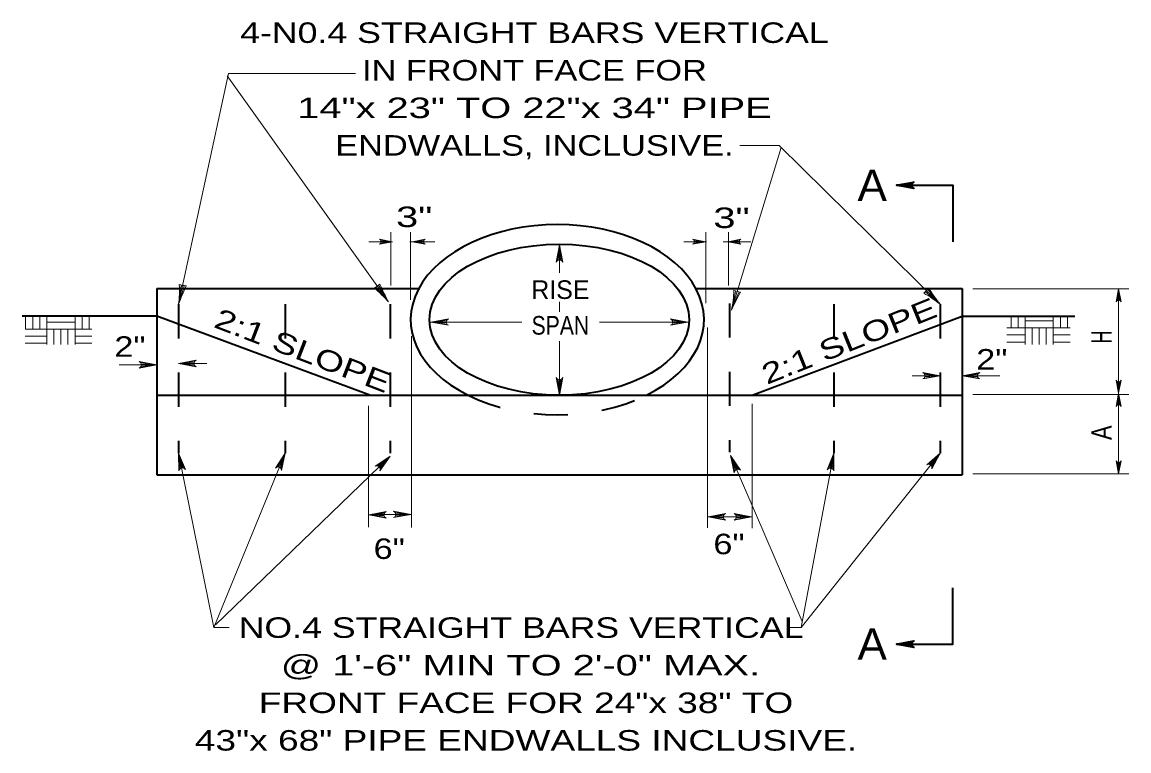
# Model space of a CAD drawing. Extents: x 394.95 to 401.96, y -76.51 to -66.78.
# Drawn here: x 395.195 to 398.432, y -71.634 to -69.501 of the extents above; entities that cross this region are included whole.
import ezdxf
from ezdxf.enums import TextEntityAlignment as Align

# ---------------------------------------------------------------- set-up
doc = ezdxf.new("R2010")
doc.units = 0
doc.header["$LTSCALE"] = 0.024
doc.linetypes.add('LONG_DASHED', pattern=[7.5, 6, -1.5])
doc.linetypes.add('MEDIUM_DASHED', pattern=[4.5, 3, -1.5])
for name, color, linetype, lineweight in [('1', 7, 'LONG_DASHED', 35), ('10', 7, 'Continuous', 13), ('13', 7, 'Continuous', 25), ('6', 7, 'Continuous', 13)]:
    doc.layers.add(name, color=color, linetype=linetype, lineweight=lineweight)
doc.layers.add('12', color=7, linetype='Continuous')

msp = doc.modelspace()

# ---------------------------------------------------------------- linework, layer by layer
at = {"layer": '1', "linetype": 'Continuous'}
for p, q in [((395.58852, -70.28099), (395.58852, -70.82641)), ((395.58852, -70.28099), (396.35718, -70.28099)), ((397.16762, -70.28099), (397.94435, -70.28099)), ((397.94435, -70.28099), (397.94435, -70.82641)), ((395.58852, -70.59266), (397.94435, -70.59266)), ((395.58852, -70.82641), (397.94435, -70.82641))]:
    msp.add_line(p, q, dxfattribs=at)
at = {"layer": '1', "linetype": 'MEDIUM_DASHED'}
for p, q in [((395.65269, -70.32682), (395.65269, -70.76224)), ((395.96435, -70.32682), (395.96435, -70.76224)), ((396.27116, -70.32682), (396.27116, -70.76224)), ((397.26408, -70.32446), (397.26408, -70.75987)), ((397.56852, -70.32682), (397.56852, -70.76224)), ((397.88019, -70.32682), (397.88019, -70.76224))]:
    msp.add_line(p, q, dxfattribs=at)
at = {"layer": '1', "linetype": 'Continuous'}
for points in [[(396.21231, -70.59266), (395.58852, -70.36187), (395.19491, -70.36187)], [(397.33013, -70.59266), (397.94435, -70.36187), (398.27364, -70.36187)]]:
    msp.add_lwpolyline(points, dxfattribs=at)
msp.add_ellipse((396.76029, -70.37184), major_axis=(0.42908, 0), ratio=0.648289, start_param=5.3652919, end_param=10.3420118, dxfattribs=at)
msp.add_ellipse((396.76595, -70.37184), major_axis=(0.37952, 0), ratio=0.582646, dxfattribs=at)
at = {"layer": '1', "linetype": 'MEDIUM_DASHED'}
msp.add_ellipse((396.76029, -70.37184), major_axis=(0.42908, 0), ratio=0.648289, start_param=4.0592877, end_param=5.364093, dxfattribs=at)
at = {"layer": '10'}
for p, q in [((396.26643, -70.31973), (395.79427, -69.65786)), ((397.26978, -70.34359), (397.41525, -69.86823)), ((397.40866, -69.86173), (397.29401, -69.86173)), ((397.88019, -70.32682), (397.40866, -69.86173)), ((396.27561, -70.14353), (396.20899, -70.14353)), ((396.27352, -70.27182), (396.27352, -70.11599)), ((396.3292, -70.14349), (396.3906, -70.14349)), ((396.33118, -70.31369), (396.33118, -70.11599)), ((396.33546, -70.14349), (396.40246, -70.14349)), ((397.1966, -70.14353), (397.12998, -70.14353)), ((397.19509, -70.32348), (397.19509, -70.11599)), ((397.24547, -70.14349), (397.30687, -70.14349)), ((397.2588, -70.14349), (397.3258, -70.14349)), ((397.2612, -70.27182), (397.2612, -70.11599)), ((395.65567, -70.30754), (395.65979, -70.27209)), ((395.65834, -70.3087), (395.66931, -70.27414)), ((396.25684, -70.30333), (396.23868, -70.27196)), ((396.25418, -70.30454), (396.23074, -70.27761)), ((397.2744, -70.32464), (397.2815, -70.28966)), ((397.27697, -70.32602), (397.29081, -70.29251)), ((397.86551, -70.31396), (397.8378, -70.29147)), ((397.86793, -70.31232), (397.84465, -70.28453)), ((398.43192, -70.28135), (397.97555, -70.28135)), ((398.40191, -70.28135), (398.40191, -70.4774)), ((396.76644, -70.34891), (396.76644, -70.31994)), ((396.3906, -70.37871), (396.65682, -70.37871)), ((396.88349, -70.37871), (397.14227, -70.37871)), ((397.1993, -70.39502), (397.1993, -70.98091)), ((396.33357, -70.42042), (396.33357, -70.97971)), ((396.76644, -70.59266), (396.76644, -70.43484)), ((395.73519, -70.50032), (395.65269, -70.50032)), ((398.40191, -70.4774), (398.40191, -70.5874)), ((395.58852, -70.50414), (395.47852, -70.50414)), ((396.76644, -70.59266), (396.75956, -70.54533)), ((396.76644, -70.54507), (396.76644, -70.56524)), ((397.88019, -70.5358), (397.79769, -70.5358)), ((398.05435, -70.5358), (397.94435, -70.5358)), ((398.43192, -70.59068), (397.97555, -70.59068)), ((398.40191, -70.5874), (398.40191, -70.71321)), ((396.20785, -70.62364), (396.20785, -70.97921)), ((397.33009, -70.61855), (397.33009, -70.98232)), ((398.40191, -70.71321), (398.40191, -70.82321)), ((395.75603, -71.27315), (395.65269, -70.76224)), ((395.96435, -70.76224), (395.75603, -71.27315)), ((396.21146, -70.82933), (396.27116, -70.7717)), ((397.33946, -70.93832), (397.26645, -70.76933)), ((397.56852, -70.76224), (397.47299, -71.27315)), ((397.473, -71.27314), (397.88019, -70.76224)), ((398.43192, -70.82321), (397.97555, -70.82321)), ((395.76014, -71.26507), (396.21146, -70.82933)), ((396.25295, -70.94298), (396.20848, -70.94298)), ((396.33258, -70.94171), (396.22258, -70.94171)), ((397.30832, -70.94866), (397.20123, -70.94866)), ((397.32832, -70.94856), (397.2822, -70.94856)), ((397.47635, -71.25516), (397.33946, -70.93832)), ((395.79999, -71.27315), (395.75603, -71.27315)), ((397.47299, -71.27315), (397.43852, -71.27315))]:
    msp.add_line(p, q, dxfattribs=at)
for points in [[(396.17019, -69.65082), (395.79836, -69.65082), (395.65269, -70.32682)], [(396.27829, -70.14349), (396.23983, -70.1507), (396.2428, -70.14865), (396.24432, -70.14607), (396.24477, -70.14349), (396.24432, -70.14092), (396.2428, -70.13833), (396.23983, -70.13628), (396.27829, -70.14349), (396.2428, -70.13833), (396.24432, -70.14092), (396.27829, -70.14349), (396.24477, -70.14349), (396.24432, -70.14607), (396.27829, -70.14349), (396.2428, -70.14865)], [(396.33546, -70.14349), (396.3739, -70.13628), (396.37095, -70.13833), (396.36941, -70.14092), (396.36897, -70.14349), (396.36941, -70.14607), (396.37095, -70.14865), (396.3739, -70.1507), (396.33546, -70.14349), (396.37095, -70.14865), (396.36941, -70.14607), (396.33546, -70.14349), (396.36897, -70.14349), (396.36941, -70.14092), (396.33546, -70.14349), (396.37095, -70.13833)], [(397.19455, -70.14349), (397.15609, -70.1507), (397.15906, -70.14865), (397.16058, -70.14607), (397.16103, -70.14349), (397.16058, -70.14092), (397.15906, -70.13833), (397.15609, -70.13628), (397.19455, -70.14349), (397.15906, -70.13833), (397.16058, -70.14092), (397.19455, -70.14349), (397.16103, -70.14349), (397.16058, -70.14607), (397.19455, -70.14349), (397.15906, -70.14865)], [(397.2588, -70.14349), (397.29724, -70.13628), (397.29429, -70.13833), (397.29275, -70.14092), (397.29231, -70.14349), (397.29275, -70.14607), (397.29429, -70.14865), (397.29724, -70.1507), (397.2588, -70.14349), (397.29429, -70.14865), (397.29275, -70.14607), (397.2588, -70.14349), (397.29231, -70.14349), (397.29275, -70.14092), (397.2588, -70.14349), (397.29429, -70.13833)], [(396.76644, -70.23516), (396.76644, -70.15266), (396.77604, -70.20393), (396.77331, -70.19997), (396.76988, -70.19793), (396.76644, -70.19734), (396.763, -70.19793), (396.75956, -70.19997), (396.75682, -70.20393), (396.76644, -70.15266), (396.75956, -70.19997), (396.763, -70.19793), (396.76644, -70.15266), (396.76644, -70.19734), (396.76988, -70.19793), (396.76644, -70.15266), (396.77331, -70.19997)], [(398.40191, -70.28135), (398.40911, -70.3198), (398.40706, -70.31684), (398.40449, -70.31531), (398.40191, -70.31488), (398.39933, -70.31531), (398.39675, -70.31684), (398.39469, -70.3198), (398.40191, -70.28135), (398.39675, -70.31684), (398.39933, -70.31531), (398.40191, -70.28135), (398.40191, -70.31488), (398.40449, -70.31531), (398.40191, -70.28135), (398.40706, -70.31684)], [(396.3906, -70.37871), (396.44186, -70.36909), (396.43792, -70.37183), (396.43588, -70.37527), (396.43529, -70.37871), (396.43588, -70.38215), (396.43792, -70.38558), (396.44186, -70.38832), (396.3906, -70.37871), (396.43792, -70.38558), (396.43588, -70.38215), (396.3906, -70.37871), (396.43529, -70.37871), (396.43588, -70.37527), (396.3906, -70.37871), (396.43792, -70.37183)], [(397.14227, -70.37871), (397.091, -70.38832), (397.09495, -70.38558), (397.09699, -70.38215), (397.09758, -70.37871), (397.09699, -70.37527), (397.09495, -70.37183), (397.091, -70.36909), (397.14227, -70.37871), (397.09495, -70.37183), (397.09699, -70.37527), (397.14227, -70.37871), (397.09758, -70.37871), (397.09699, -70.38215), (397.14227, -70.37871), (397.09495, -70.38558)], [(395.58852, -70.50414), (395.53725, -70.51375), (395.5412, -70.51101), (395.54324, -70.50757), (395.54383, -70.50414), (395.54324, -70.5007), (395.5412, -70.49726), (395.53725, -70.49452), (395.58852, -70.50414), (395.5412, -70.49726), (395.54324, -70.5007), (395.58852, -70.50414), (395.54383, -70.50414), (395.54324, -70.50757), (395.58852, -70.50414), (395.5412, -70.51101)], [(395.65269, -70.50032), (395.70395, -70.49071), (395.7, -70.49345), (395.69796, -70.49689), (395.69737, -70.50032), (395.69796, -70.50376), (395.7, -70.5072), (395.70395, -70.50994), (395.65269, -70.50032), (395.7, -70.5072), (395.69796, -70.50376), (395.65269, -70.50032), (395.69737, -70.50032), (395.69796, -70.49689), (395.65269, -70.50032), (395.7, -70.49345)], [(397.88019, -70.53579), (397.82892, -70.54541), (397.83286, -70.54267), (397.83491, -70.53923), (397.8355, -70.53579), (397.83491, -70.53235), (397.83286, -70.52892), (397.82892, -70.52618), (397.88019, -70.53579), (397.83286, -70.52892), (397.83491, -70.53235), (397.88019, -70.53579), (397.8355, -70.53579), (397.83491, -70.53923), (397.88019, -70.53579), (397.83286, -70.54267)], [(397.94435, -70.53579), (397.99561, -70.52618), (397.99167, -70.52892), (397.98962, -70.53235), (397.98904, -70.53579), (397.98962, -70.53923), (397.99167, -70.54267), (397.99561, -70.54541), (397.94435, -70.53579), (397.99167, -70.54267), (397.98962, -70.53923), (397.94435, -70.53579), (397.98904, -70.53579), (397.98962, -70.53235), (397.94435, -70.53579), (397.99167, -70.52892)], [(398.40191, -70.5874), (398.39469, -70.54896), (398.39675, -70.55192), (398.39933, -70.55345), (398.40191, -70.55389), (398.40449, -70.55345), (398.40706, -70.55192), (398.40911, -70.54896), (398.40191, -70.5874), (398.40706, -70.55192), (398.40449, -70.55345), (398.40191, -70.5874), (398.40191, -70.55389), (398.39933, -70.55345), (398.40191, -70.5874), (398.39675, -70.55192)], [(398.40191, -70.5874), (398.40911, -70.62585), (398.40706, -70.62289), (398.40449, -70.62136), (398.40191, -70.62092), (398.39933, -70.62136), (398.39675, -70.62289), (398.39469, -70.62585), (398.40191, -70.5874), (398.39675, -70.62289), (398.39933, -70.62136), (398.40191, -70.5874), (398.40191, -70.62092), (398.40449, -70.62136), (398.40191, -70.5874), (398.40706, -70.62289)], [(395.65269, -70.76224), (395.67227, -70.81057), (395.66879, -70.80725), (395.66503, -70.80594), (395.66154, -70.80603), (395.65829, -70.80729), (395.65532, -70.80998), (395.65342, -70.81439), (395.65269, -70.76224), (395.65532, -70.80998), (395.65829, -70.80729), (395.65269, -70.76224), (395.66154, -70.80603), (395.66503, -70.80594), (395.65269, -70.76224), (395.66879, -70.80725)], [(395.96435, -70.76224), (395.9539, -70.81333), (395.95284, -70.80865), (395.95044, -70.80546), (395.94748, -70.80361), (395.94407, -70.80286), (395.94011, -70.80346), (395.93609, -70.80608), (395.96435, -70.76224), (395.94011, -70.80346), (395.94407, -70.80286), (395.96435, -70.76224), (395.94748, -70.80361), (395.95044, -70.80546), (395.96435, -70.76224), (395.95284, -70.80865)], [(396.27116, -70.7717), (396.24095, -70.81422), (396.24189, -70.8095), (396.24096, -70.80561), (396.239, -70.80274), (396.2362, -70.80067), (396.23233, -70.79961), (396.22759, -70.8004), (396.27116, -70.7717), (396.23233, -70.79961), (396.2362, -70.80067), (396.27116, -70.7717), (396.239, -70.80274), (396.24096, -70.80561), (396.27116, -70.7717), (396.24189, -70.8095)], [(397.26645, -70.76933), (397.29559, -70.81258), (397.29152, -70.81003), (397.28755, -70.80953), (397.28416, -70.81035), (397.28125, -70.81226), (397.27891, -70.81549), (397.27795, -70.8202), (397.26645, -70.76933), (397.27891, -70.81549), (397.28125, -70.81226), (397.26645, -70.76933), (397.28416, -70.81035), (397.28755, -70.80953), (397.26645, -70.76933), (397.29152, -70.81003)], [(397.56852, -70.76224), (397.56854, -70.8144), (397.56658, -70.81001), (397.56357, -70.80737), (397.5603, -70.80617), (397.55682, -70.80611), (397.55306, -70.80748), (397.54965, -70.81086), (397.56852, -70.76224), (397.55306, -70.80748), (397.55682, -70.80611), (397.56852, -70.76224), (397.5603, -70.80617), (397.56357, -70.80737), (397.56852, -70.76224), (397.56658, -70.81001)], [(397.88019, -70.76224), (397.84071, -70.79634), (397.84532, -70.79496), (397.84927, -70.79551), (397.85233, -70.79719), (397.85465, -70.79979), (397.85606, -70.80353), (397.85575, -70.80831), (397.88019, -70.76224), (397.85606, -70.80353), (397.85465, -70.79979), (397.88019, -70.76224), (397.85233, -70.79719), (397.84927, -70.79551), (397.88019, -70.76224), (397.84532, -70.79496)], [(398.40191, -70.82321), (398.39469, -70.78477), (398.39675, -70.78773), (398.39933, -70.78926), (398.40191, -70.7897), (398.40449, -70.78926), (398.40706, -70.78773), (398.40911, -70.78477), (398.40191, -70.82321), (398.40706, -70.78773), (398.40449, -70.78926), (398.40191, -70.82321), (398.40191, -70.7897), (398.39933, -70.78926), (398.40191, -70.82321), (398.39675, -70.78773)], [(396.20848, -70.94298), (396.25974, -70.93336), (396.25579, -70.9361), (396.25375, -70.93954), (396.25317, -70.94298), (396.25375, -70.94642), (396.25579, -70.94985), (396.25974, -70.95259), (396.20848, -70.94298), (396.25579, -70.94985), (396.25375, -70.94642), (396.20848, -70.94298), (396.25317, -70.94298), (396.25375, -70.93954), (396.20848, -70.94298), (396.25579, -70.9361)], [(396.33258, -70.94171), (396.28131, -70.95132), (396.28526, -70.94858), (396.2873, -70.94515), (396.2879, -70.94171), (396.2873, -70.93827), (396.28526, -70.93483), (396.28131, -70.93209), (396.33258, -70.94171), (396.28526, -70.93483), (396.2873, -70.93827), (396.33258, -70.94171), (396.2879, -70.94171), (396.2873, -70.94515), (396.33258, -70.94171), (396.28526, -70.94858)], [(397.20123, -70.94866), (397.25249, -70.93904), (397.24854, -70.94178), (397.2465, -70.94522), (397.24592, -70.94866), (397.2465, -70.95209), (397.24854, -70.95553), (397.25249, -70.95827), (397.20123, -70.94866), (397.24854, -70.95553), (397.2465, -70.95209), (397.20123, -70.94866), (397.24592, -70.94866), (397.2465, -70.94522), (397.20123, -70.94866), (397.24854, -70.94178)], [(397.32832, -70.94856), (397.27705, -70.95818), (397.281, -70.95544), (397.28304, -70.952), (397.28364, -70.94856), (397.28304, -70.94513), (397.281, -70.94169), (397.27705, -70.93895), (397.32832, -70.94856), (397.281, -70.94169), (397.28304, -70.94513), (397.32832, -70.94856), (397.28364, -70.94856), (397.28304, -70.952), (397.32832, -70.94856), (397.281, -70.95544)]]:
    msp.add_lwpolyline(points, dxfattribs=at)
at = {"layer": '10', "lineweight": 35}
for points in [[(397.75185, -69.97849), (397.80311, -69.96887), (397.79917, -69.97161), (397.79712, -69.97505), (397.79654, -69.97849), (397.79712, -69.98193), (397.79917, -69.98536), (397.80311, -69.9881), (397.75185, -69.97849), (397.79917, -69.98536), (397.79712, -69.98193), (397.75185, -69.97849), (397.79654, -69.97849), (397.79712, -69.97505), (397.75185, -69.97849), (397.79917, -69.97161)], [(397.75185, -69.97849), (397.91685, -69.97849), (397.91685, -70.14349)], [(397.75185, -71.32141), (397.91685, -71.32141), (397.91685, -71.15641)], [(397.75185, -71.32141), (397.80311, -71.31179), (397.79917, -71.31453), (397.79712, -71.31797), (397.79654, -71.32141), (397.79712, -71.32484), (397.79917, -71.32828), (397.80311, -71.33102), (397.75185, -71.32141), (397.79917, -71.32828), (397.79712, -71.32484), (397.75185, -71.32141), (397.79654, -71.32141), (397.79712, -71.31797), (397.75185, -71.32141), (397.79917, -71.31453)]]:
    msp.add_lwpolyline(points, dxfattribs=at)
at = {"layer": '10'}
for points in [[(396.76644, -70.59266), (396.75682, -70.5414), (396.75956, -70.54533), (396.763, -70.54738), (396.76644, -70.54797), (396.76988, -70.54738), (396.77331, -70.54533), (396.77604, -70.5414)], [(396.76644, -70.59266), (396.76644, -70.54797), (396.763, -70.54738)], [(396.76644, -70.59266), (396.77331, -70.54533), (396.76988, -70.54738)]]:
    msp.add_lwpolyline(points, close=True, dxfattribs=at)
for centre, radius, start, end in [((395.2625, -70.28436), 0.39248, 353.78922, 2.29506), ((396.24783, -70.53368), 0.63007, 155.54689, 160.83336), ((395.68288, -70.18534), 0.08794, 251.29188, 264.38446), ((396.18218, -70.20212), 0.08794, 298.95583, 312.04841), ((396.82015, -70.01911), 0.63007, 203.21084, 208.49731), ((395.97226, -70.57955), 0.39248, 41.45317, 49.95901), ((397.8453, -70.60005), 0.63007, 150.69521, 155.98168), ((396.8846, -70.26828), 0.39248, 348.93755, 357.44338), ((397.31184, -70.20518), 0.08794, 246.4402, 259.53278), ((397.77699, -70.22544), 0.08794, 308.84748, 321.94006), ((397.63503, -70.63332), 0.39248, 51.34482, 59.85066), ((398.37404, -69.93555), 0.63007, 213.10249, 218.38896)]:
    msp.add_arc(centre, radius, start, end, dxfattribs=at)
at = {"layer": '6'}
for p, q in [((395.20523, -70.39977), (395.20523, -70.36187)), ((395.22585, -70.39977), (395.22585, -70.36187)), ((395.24648, -70.39977), (395.24648, -70.36187)), ((395.3496, -70.39977), (395.3496, -70.36187)), ((395.37023, -70.39977), (395.37023, -70.36187)), ((395.39085, -70.39977), (395.39085, -70.36187)), ((398.08724, -70.39593), (398.08724, -70.36187)), ((398.10786, -70.39593), (398.10786, -70.36187)), ((398.12849, -70.39593), (398.12849, -70.36187)), ((398.21099, -70.39593), (398.21099, -70.36187)), ((398.23161, -70.39593), (398.23161, -70.36187)), ((398.25224, -70.39593), (398.25224, -70.36187)), ((395.2671, -70.37915), (395.3496, -70.37915)), ((395.28773, -70.44437), (395.28773, -70.39977)), ((395.30835, -70.44437), (395.30835, -70.39977)), ((395.32898, -70.44437), (395.32898, -70.39977)), ((395.3496, -70.44437), (395.3496, -70.39977)), ((395.3496, -70.39977), (395.39874, -70.39977)), ((398.07489, -70.39593), (398.12849, -70.39593)), ((398.12849, -70.3753), (398.21099, -70.3753)), ((398.12849, -70.44437), (398.12849, -70.39593)), ((398.12849, -70.39593), (398.21099, -70.39593)), ((398.14911, -70.44437), (398.14911, -70.39593)), ((398.16974, -70.44437), (398.16974, -70.39593)), ((398.19036, -70.44437), (398.19036, -70.39593)), ((398.21099, -70.44437), (398.21099, -70.39593)), ((398.21099, -70.39593), (398.25997, -70.39593)), ((395.20343, -70.4204), (395.2671, -70.4204)), ((395.3496, -70.4204), (395.39874, -70.4204)), ((398.07489, -70.41655), (398.12849, -70.41655)), ((398.07489, -70.43718), (398.12849, -70.43718)), ((398.21099, -70.41655), (398.25997, -70.41655)), ((398.21099, -70.43718), (398.25997, -70.43718)), ((395.20343, -70.44102), (395.2671, -70.44102)), ((395.3496, -70.44102), (395.39874, -70.44102))]:
    msp.add_line(p, q, dxfattribs=at)
for points in [[(395.2671, -70.44437), (395.2671, -70.39977), (395.2671, -70.36187)], [(395.20343, -70.39977), (395.2671, -70.39977), (395.3496, -70.39977)]]:
    msp.add_lwpolyline(points, dxfattribs=at)

# ---------------------------------------------------------------- texts
at = {"layer": '12'}
for s, height, width, p in [('4-N0.4 STRAIGHT BARS VERTICAL', 0.06, 1.3, (396.69337, -69.56173)), ('IN FRONT FACE FOR', 0.06, 1.25, (396.69338, -69.67173)), ('14"x 23" TO 22"x 34" PIPE', 0.06, 1.45, (396.69336, -69.78173)), ('ENDWALLS, INCLUSIVE.', 0.06, 1.25, (396.69336, -69.89173)), ('3"', 0.06, 1.45, (396.34162, -70.10073)), ('3"', 0.06, 1.45, (397.26966, -70.1036)), ('SPAN', 0.05445, 0.85, (396.76917, -70.4156)), ('2"', 0.06, 1.25, (395.51024, -70.48044)), ('2"', 0.06, 1.25, (398.03107, -70.51784)), ('6"', 0.06, 1.25, (396.2686, -71.07221)), ('6"', 0.06, 1.25, (397.26234, -71.05836)), ('NO.4 STRAIGHT BARS VERTICAL ', 0.06, 1.3, (396.66862, -71.30314)), ('@ 1\'-6" MIN TO 2\'-0" MAX. ', 0.06, 1.45, (396.66862, -71.41314)), ('FRONT FACE FOR 24"x 38" TO', 0.06, 1.35, (396.66862, -71.52314)), ('43"x 68" PIPE ENDWALLS INCLUSIVE.', 0.06, 1.35, (396.66861, -71.63314))]:
    msp.add_text(s, height=height, dxfattribs=dict(at, width=width)).set_placement(p, align=Align.CENTER)
msp.add_text('RISE', height=0.05445, dxfattribs=at).set_placement((396.76916, -70.31115), align=Align.CENTER)
for s, rotation, width, p in [('2:1 SLOPE', 21.827, 1.35, (397.62454, -70.46214)), ('2:1 SLOPE', 338.932, 1.35, (396.00488, -70.49016)), ('H', 90, 0.65, (398.38192, -70.42279)), ('A', 90, 0.8, (398.38192, -70.70269))]:
    msp.add_text(s, height=0.06, rotation=rotation, dxfattribs=dict(at, width=width)).set_placement(p, align=Align.CENTER)
at = {"layer": '13', "width": 1.05}
for p in [(397.72434, -70.02454), (397.72434, -71.36746)]:
    msp.add_text('A', height=0.09213, dxfattribs=at).set_placement(p, align=Align.RIGHT)

doc.saveas('drawing.dxf')
